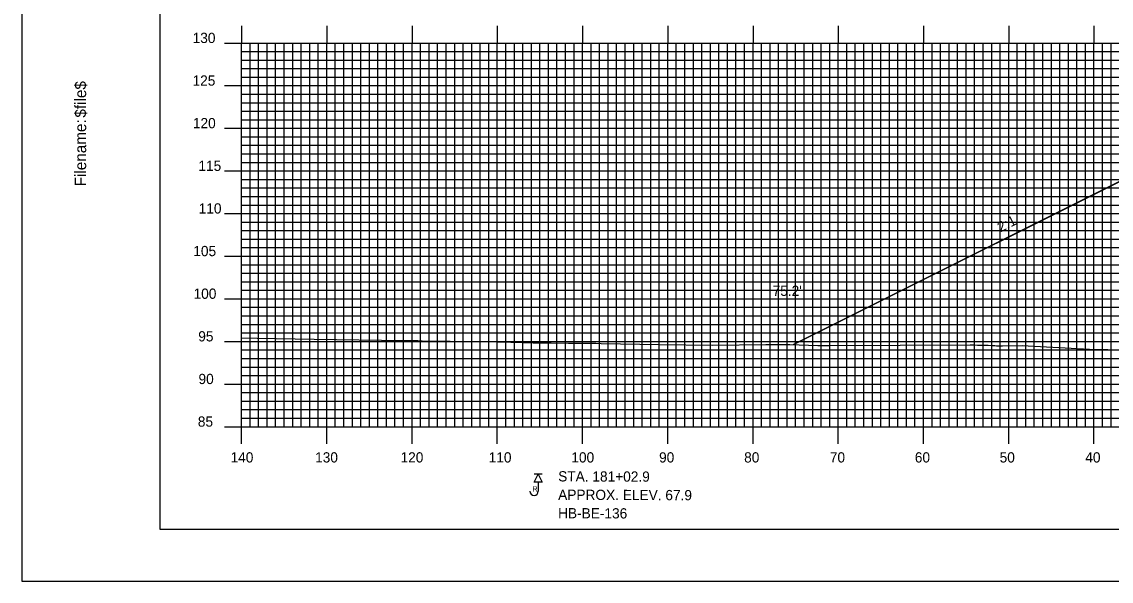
# Model space of a CAD drawing. Extents: x 1786189 to 1786532, y 442591 to 442811.
# Drawn here: x 1786188.8 to 1786316.6, y 442590.5 to 442656.2 of the extents above; entities that cross this region are included whole.
import ezdxf

# ---------------------------------------------------------------- set-up
doc = ezdxf.new("R2010")
doc.units = 0
for name, color, linetype in [('ANNOTATION', 7, 'Continuous'), ('BORDER', 7, 'Continuous'), ('BORING - REFUSAL', 7, 'Continuous'), ('D_Roadway_Centerline', 7, 'Continuous'), ('D_Roadway_SlopeLines', 7, 'Continuous'), ('D_Text_Standard', 7, 'Continuous'), ('H_V ANNOTATION', 7, 'Continuous'), ('MAJOR', 7, 'Continuous'), ('MINOR', 7, 'Continuous'), ('PLOT BOUNDARY', 7, 'Continuous'), ('S_Roadway_Centerline', 7, 'Continuous')]:
    doc.layers.add(name, color=color, linetype=linetype)

msp = doc.modelspace()

# ---------------------------------------------------------------- linework, layer by layer
at = {"layer": 'BORDER'}
msp.add_lwpolyline([(1786204.96, 442596.67), (1786524.96, 442596.67), (1786524.96, 442806.67), (1786204.96, 442806.67)], close=True, dxfattribs=at)
at = {"layer": 'BORING - REFUSAL'}
for p, q in [((1786249.84, 442603.12), (1786248.89, 442603.12)), ((1786249.36, 442602.16), (1786249.36, 442601.1))]:
    msp.add_line(p, q, dxfattribs=at)
msp.add_lwpolyline([(1786249.36, 442603.12), (1786249.84, 442602.16), (1786248.89, 442602.16)], close=True, dxfattribs=at)
msp.add_arc((1786248.88, 442601.1), 0.485, 180, 0, dxfattribs=at)
at = {"layer": 'D_Roadway_Centerline'}
msp.add_lwpolyline([(1786279.32, 442618.29), (1786326.75, 442642), (1786331.56, 442644.41), (1786334.56, 442644.53), (1786342.56, 442644.85), (1786354.56, 442645.11), (1786366.56, 442645.37), (1786374.56, 442645.05), (1786377.56, 442644.93), (1786382.31, 442642.56), (1786433.18, 442617.13)], dxfattribs=at)
at = {"layer": 'D_Roadway_SlopeLines'}
msp.add_lwpolyline([(1786331.56, 442644.41), (1786279.32, 442618.29)], dxfattribs=at)
at = {"layer": 'MAJOR'}
for p, q in [((1786214.56, 442655.67), (1786214.56, 442653.67)), ((1786224.56, 442655.67), (1786224.56, 442653.67)), ((1786234.56, 442655.67), (1786234.56, 442653.67)), ((1786244.56, 442655.67), (1786244.56, 442653.67)), ((1786254.56, 442655.67), (1786254.56, 442653.67)), ((1786264.56, 442655.67), (1786264.56, 442653.67)), ((1786274.56, 442655.67), (1786274.56, 442653.67)), ((1786284.56, 442655.67), (1786284.56, 442653.67)), ((1786294.56, 442655.67), (1786294.56, 442653.67)), ((1786304.56, 442655.67), (1786304.56, 442653.67)), ((1786314.56, 442655.67), (1786314.56, 442653.67)), ((1786212.56, 442653.67), (1786214.56, 442653.67)), ((1786214.56, 442653.67), (1786494.56, 442653.67)), ((1786214.56, 442608.67), (1786214.56, 442653.67)), ((1786214.56, 442608.67), (1786214.56, 442653.67)), ((1786214.56, 442653.67), (1786494.56, 442653.67)), ((1786224.56, 442608.67), (1786224.56, 442653.67)), ((1786234.56, 442608.67), (1786234.56, 442653.67)), ((1786244.56, 442608.67), (1786244.56, 442653.67)), ((1786254.56, 442608.67), (1786254.56, 442653.67)), ((1786264.56, 442608.67), (1786264.56, 442653.67)), ((1786274.56, 442608.67), (1786274.56, 442653.67)), ((1786284.56, 442608.67), (1786284.56, 442653.67)), ((1786294.56, 442608.67), (1786294.56, 442653.67)), ((1786304.56, 442608.67), (1786304.56, 442653.67)), ((1786314.56, 442608.67), (1786314.56, 442653.67)), ((1786212.56, 442648.67), (1786214.56, 442648.67)), ((1786214.56, 442648.67), (1786494.56, 442648.67)), ((1786212.56, 442643.67), (1786214.56, 442643.67)), ((1786214.56, 442643.67), (1786494.56, 442643.67)), ((1786212.56, 442638.67), (1786214.56, 442638.67)), ((1786214.56, 442638.67), (1786494.56, 442638.67)), ((1786212.56, 442633.67), (1786214.56, 442633.67)), ((1786214.56, 442633.67), (1786494.56, 442633.67)), ((1786212.56, 442628.67), (1786214.56, 442628.67)), ((1786214.56, 442628.67), (1786494.56, 442628.67)), ((1786212.56, 442623.67), (1786214.56, 442623.67)), ((1786214.56, 442623.67), (1786494.56, 442623.67)), ((1786212.56, 442618.67), (1786214.56, 442618.67)), ((1786214.56, 442618.67), (1786494.56, 442618.67)), ((1786212.56, 442613.67), (1786214.56, 442613.67)), ((1786214.56, 442613.67), (1786494.56, 442613.67)), ((1786212.56, 442608.67), (1786214.56, 442608.67)), ((1786214.56, 442608.67), (1786494.56, 442608.67)), ((1786214.56, 442608.67), (1786494.56, 442608.67)), ((1786214.56, 442606.66), (1786214.56, 442608.67)), ((1786224.56, 442606.66), (1786224.56, 442608.67)), ((1786234.56, 442606.66), (1786234.56, 442608.67)), ((1786244.56, 442606.66), (1786244.56, 442608.67)), ((1786254.56, 442606.66), (1786254.56, 442608.67)), ((1786264.56, 442606.66), (1786264.56, 442608.67)), ((1786274.56, 442606.66), (1786274.56, 442608.67)), ((1786284.56, 442606.66), (1786284.56, 442608.67)), ((1786294.56, 442606.66), (1786294.56, 442608.67)), ((1786304.56, 442606.66), (1786304.56, 442608.67)), ((1786314.56, 442606.66), (1786314.56, 442608.67))]:
    msp.add_line(p, q, dxfattribs=at)
at = {"layer": 'MINOR'}
for p, q in [((1786214.56, 442652.67), (1786494.56, 442652.67)), ((1786214.56, 442652.67), (1786216.57, 442652.67)), ((1786215.56, 442608.67), (1786215.56, 442653.67)), ((1786216.56, 442608.67), (1786216.56, 442653.67)), ((1786217.56, 442608.67), (1786217.56, 442653.67)), ((1786218.56, 442608.67), (1786218.56, 442653.67)), ((1786219.56, 442608.67), (1786219.56, 442653.67)), ((1786220.56, 442608.67), (1786220.56, 442653.67)), ((1786221.56, 442608.67), (1786221.56, 442653.67)), ((1786222.56, 442608.67), (1786222.56, 442653.67)), ((1786223.56, 442608.67), (1786223.56, 442653.67)), ((1786225.56, 442608.67), (1786225.56, 442653.67)), ((1786226.56, 442608.67), (1786226.56, 442653.67)), ((1786227.56, 442608.67), (1786227.56, 442653.67)), ((1786228.56, 442608.67), (1786228.56, 442653.67)), ((1786229.56, 442608.67), (1786229.56, 442653.67)), ((1786230.56, 442608.67), (1786230.56, 442653.67)), ((1786231.56, 442608.67), (1786231.56, 442653.67)), ((1786232.56, 442608.67), (1786232.56, 442653.67)), ((1786233.56, 442608.67), (1786233.56, 442653.67)), ((1786235.56, 442608.67), (1786235.56, 442653.67)), ((1786236.56, 442608.67), (1786236.56, 442653.67)), ((1786237.56, 442608.67), (1786237.56, 442653.67)), ((1786238.56, 442608.67), (1786238.56, 442653.67)), ((1786239.56, 442608.67), (1786239.56, 442653.67)), ((1786240.56, 442608.67), (1786240.56, 442653.67)), ((1786241.56, 442608.67), (1786241.56, 442653.67)), ((1786242.56, 442608.67), (1786242.56, 442653.67)), ((1786243.56, 442608.67), (1786243.56, 442653.67)), ((1786245.56, 442608.67), (1786245.56, 442653.67)), ((1786246.56, 442608.67), (1786246.56, 442653.67)), ((1786247.56, 442608.67), (1786247.56, 442653.67)), ((1786248.56, 442608.67), (1786248.56, 442653.67)), ((1786249.56, 442608.67), (1786249.56, 442653.67)), ((1786250.56, 442608.67), (1786250.56, 442653.67)), ((1786251.56, 442608.67), (1786251.56, 442653.67)), ((1786252.56, 442608.67), (1786252.56, 442653.67)), ((1786253.56, 442608.67), (1786253.56, 442653.67)), ((1786255.56, 442608.67), (1786255.56, 442653.67)), ((1786256.56, 442608.67), (1786256.56, 442653.67)), ((1786257.56, 442608.67), (1786257.56, 442653.67)), ((1786258.56, 442608.67), (1786258.56, 442653.67)), ((1786259.56, 442608.67), (1786259.56, 442653.67)), ((1786260.56, 442608.67), (1786260.56, 442653.67)), ((1786261.56, 442608.67), (1786261.56, 442653.67)), ((1786262.56, 442608.67), (1786262.56, 442653.67)), ((1786263.56, 442608.67), (1786263.56, 442653.67)), ((1786265.56, 442608.67), (1786265.56, 442653.67)), ((1786266.56, 442608.67), (1786266.56, 442653.67)), ((1786267.56, 442608.67), (1786267.56, 442653.67)), ((1786268.56, 442608.67), (1786268.56, 442653.67)), ((1786269.56, 442608.67), (1786269.56, 442653.67)), ((1786270.56, 442608.67), (1786270.56, 442653.67)), ((1786271.56, 442608.67), (1786271.56, 442653.67)), ((1786272.56, 442608.67), (1786272.56, 442653.67)), ((1786273.56, 442608.67), (1786273.56, 442653.67)), ((1786275.56, 442608.67), (1786275.56, 442653.67)), ((1786276.56, 442608.67), (1786276.56, 442653.67)), ((1786277.56, 442608.67), (1786277.56, 442653.67)), ((1786278.56, 442608.67), (1786278.56, 442653.67)), ((1786279.56, 442608.67), (1786279.56, 442653.67)), ((1786280.56, 442608.67), (1786280.56, 442653.67)), ((1786281.56, 442608.67), (1786281.56, 442653.67)), ((1786282.56, 442608.67), (1786282.56, 442653.67)), ((1786283.56, 442608.67), (1786283.56, 442653.67)), ((1786285.56, 442608.67), (1786285.56, 442653.67)), ((1786286.56, 442608.67), (1786286.56, 442653.67)), ((1786287.56, 442608.67), (1786287.56, 442653.67)), ((1786288.56, 442608.67), (1786288.56, 442653.67)), ((1786289.56, 442608.67), (1786289.56, 442653.67)), ((1786290.56, 442608.67), (1786290.56, 442653.67)), ((1786291.56, 442608.67), (1786291.56, 442653.67)), ((1786292.56, 442608.67), (1786292.56, 442653.67)), ((1786293.56, 442608.67), (1786293.56, 442653.67)), ((1786295.56, 442608.67), (1786295.56, 442653.67)), ((1786296.56, 442608.67), (1786296.56, 442653.67)), ((1786297.56, 442608.67), (1786297.56, 442653.67)), ((1786298.56, 442608.67), (1786298.56, 442653.67)), ((1786299.56, 442608.67), (1786299.56, 442653.67)), ((1786300.56, 442608.67), (1786300.56, 442653.67)), ((1786301.56, 442608.67), (1786301.56, 442653.67)), ((1786302.56, 442608.67), (1786302.56, 442653.67)), ((1786303.56, 442608.67), (1786303.56, 442653.67)), ((1786305.56, 442608.67), (1786305.56, 442653.67)), ((1786306.56, 442608.67), (1786306.56, 442653.67)), ((1786307.56, 442608.67), (1786307.56, 442653.67)), ((1786308.56, 442608.67), (1786308.56, 442653.67)), ((1786309.56, 442608.67), (1786309.56, 442653.67)), ((1786310.56, 442608.67), (1786310.56, 442653.67)), ((1786311.56, 442608.67), (1786311.56, 442653.67)), ((1786312.56, 442608.67), (1786312.56, 442653.67)), ((1786313.56, 442608.67), (1786313.56, 442653.67)), ((1786315.56, 442608.67), (1786315.56, 442653.67)), ((1786316.56, 442608.67), (1786316.56, 442653.67)), ((1786214.56, 442651.67), (1786494.56, 442651.67)), ((1786214.56, 442651.67), (1786216.57, 442651.67)), ((1786214.56, 442650.67), (1786494.56, 442650.67)), ((1786214.56, 442650.67), (1786216.57, 442650.67)), ((1786214.56, 442649.67), (1786494.56, 442649.67)), ((1786214.56, 442649.67), (1786216.57, 442649.67)), ((1786214.56, 442647.67), (1786494.56, 442647.67)), ((1786214.56, 442647.67), (1786216.57, 442647.67)), ((1786214.56, 442646.67), (1786494.56, 442646.67)), ((1786214.56, 442646.67), (1786216.57, 442646.67)), ((1786214.56, 442645.67), (1786494.56, 442645.67)), ((1786214.56, 442645.67), (1786216.57, 442645.67)), ((1786214.56, 442644.67), (1786494.56, 442644.67)), ((1786214.56, 442644.67), (1786216.57, 442644.67)), ((1786214.56, 442642.67), (1786494.56, 442642.67)), ((1786214.56, 442642.67), (1786216.57, 442642.67)), ((1786214.56, 442641.67), (1786494.56, 442641.67)), ((1786214.56, 442641.67), (1786216.57, 442641.67)), ((1786214.56, 442640.67), (1786494.56, 442640.67)), ((1786214.56, 442640.67), (1786216.57, 442640.67)), ((1786214.56, 442639.67), (1786494.56, 442639.67)), ((1786214.56, 442639.67), (1786216.57, 442639.67)), ((1786214.56, 442637.67), (1786494.56, 442637.67)), ((1786214.56, 442637.67), (1786216.57, 442637.67)), ((1786214.56, 442636.67), (1786494.56, 442636.67)), ((1786214.56, 442636.67), (1786216.57, 442636.67)), ((1786214.56, 442635.67), (1786494.56, 442635.67)), ((1786214.56, 442635.67), (1786216.57, 442635.67)), ((1786214.56, 442634.67), (1786494.56, 442634.67)), ((1786214.56, 442634.67), (1786216.57, 442634.67)), ((1786214.56, 442632.67), (1786494.56, 442632.67)), ((1786214.56, 442632.67), (1786216.57, 442632.67)), ((1786214.56, 442631.67), (1786494.56, 442631.67)), ((1786214.56, 442631.67), (1786216.57, 442631.67)), ((1786214.56, 442630.67), (1786494.56, 442630.67)), ((1786214.56, 442630.67), (1786216.57, 442630.67)), ((1786214.56, 442629.67), (1786494.56, 442629.67)), ((1786214.56, 442629.67), (1786216.57, 442629.67)), ((1786214.56, 442627.67), (1786494.56, 442627.67)), ((1786214.56, 442627.67), (1786216.57, 442627.67)), ((1786214.56, 442626.67), (1786494.56, 442626.67)), ((1786214.56, 442626.67), (1786216.57, 442626.67)), ((1786214.56, 442625.67), (1786494.56, 442625.67)), ((1786214.56, 442625.67), (1786216.57, 442625.67)), ((1786214.56, 442624.67), (1786494.56, 442624.67)), ((1786214.56, 442624.67), (1786216.57, 442624.67)), ((1786214.56, 442622.67), (1786494.56, 442622.67)), ((1786214.56, 442622.67), (1786216.57, 442622.67)), ((1786214.56, 442621.67), (1786494.56, 442621.67)), ((1786214.56, 442621.67), (1786216.57, 442621.67)), ((1786214.56, 442620.67), (1786494.56, 442620.67)), ((1786214.56, 442620.67), (1786216.57, 442620.67)), ((1786214.56, 442619.67), (1786494.56, 442619.67)), ((1786214.56, 442619.67), (1786216.57, 442619.67)), ((1786214.56, 442617.67), (1786494.56, 442617.67)), ((1786214.56, 442617.67), (1786216.57, 442617.67)), ((1786214.56, 442616.67), (1786494.56, 442616.67)), ((1786214.56, 442616.67), (1786216.57, 442616.67)), ((1786214.56, 442615.67), (1786494.56, 442615.67)), ((1786214.56, 442615.67), (1786216.57, 442615.67)), ((1786214.56, 442614.67), (1786494.56, 442614.67)), ((1786214.56, 442614.67), (1786216.57, 442614.67)), ((1786214.56, 442612.67), (1786494.56, 442612.67)), ((1786214.56, 442612.67), (1786216.57, 442612.67)), ((1786214.56, 442611.67), (1786494.56, 442611.67)), ((1786214.56, 442611.67), (1786216.57, 442611.67)), ((1786214.56, 442610.67), (1786494.56, 442610.67)), ((1786214.56, 442610.67), (1786216.57, 442610.67)), ((1786214.56, 442609.67), (1786494.56, 442609.67)), ((1786214.56, 442609.67), (1786216.57, 442609.67))]:
    msp.add_line(p, q, dxfattribs=at)
at = {"layer": 'PLOT BOUNDARY'}
msp.add_lwpolyline([(1786188.78, 442590.55), (1786528.78, 442590.55), (1786528.78, 442810.55), (1786188.78, 442810.55)], close=True, dxfattribs=at)
at = {"layer": 'S_Roadway_Centerline'}
msp.add_lwpolyline([(1786214.56, 442619.08), (1786216.39, 442619.05), (1786223.08, 442618.95), (1786233.58, 442618.78), (1786233.92, 442618.77), (1786234.31, 442618.77), (1786234.74, 442618.76), (1786235.22, 442618.76), (1786235.74, 442618.75), (1786242.33, 442618.68), (1786243.04, 442618.68), (1786246.13, 442618.6), (1786248.76, 442618.52), (1786250.88, 442618.5), (1786252.92, 442618.48), (1786253.84, 442618.47), (1786254.68, 442618.46), (1786255.44, 442618.45), (1786256.13, 442618.45), (1786256.74, 442618.44), (1786263.54, 442618.3), (1786269.84, 442618.23), (1786276.05, 442618.29), (1786278.86, 442618.3), (1786282.15, 442618.19), (1786282.33, 442618.19), (1786282.51, 442618.19), (1786282.69, 442618.19), (1786282.87, 442618.19), (1786283.04, 442618.19), (1786283.19, 442618.18), (1786283.4, 442618.18), (1786283.62, 442618.18), (1786300.03, 442618.26), (1786300.19, 442618.26), (1786300.36, 442618.26), (1786300.53, 442618.26), (1786300.88, 442618.25), (1786301.05, 442618.25), (1786301.79, 442618.23), (1786301.96, 442618.23), (1786302.14, 442618.22), (1786302.51, 442618.2), (1786302.71, 442618.19), (1786302.91, 442618.18), (1786303.11, 442618.17), (1786303.3, 442618.17), (1786303.47, 442618.16), (1786303.65, 442618.16), (1786303.84, 442618.16), (1786306.14, 442618.21), (1786314.04, 442617.77), (1786324.86, 442617.57)], dxfattribs=at)

# ---------------------------------------------------------------- texts
at = {"layer": 'ANNOTATION'}
msp.add_text('2:1', height=1.2, rotation=26.5651, dxfattribs=at).set_placement((1786303.59, 442631.45))
at = {"layer": 'BORDER'}
for s, p in [('$file$', (1786196.33, 442644.92)), ('Filename:', (1786196.33, 442636.86))]:
    msp.add_text(s, height=1.339, rotation=90, dxfattribs=at).set_placement(p)
at = {"layer": 'BORING - REFUSAL'}
for s, p in [('STA. 181+02.9', (1786251.7, 442602.25)), ('APPROX. ELEV. 67.9', (1786251.7, 442600.09)), ('HB-BE-136', (1786251.69, 442597.93))]:
    msp.add_text(s, height=1.2, rotation=359.8142, dxfattribs=at).set_placement(p)
msp.add_text('R', height=0.64, dxfattribs=at).set_placement((1786248.66, 442601.05))
at = {"layer": 'D_Text_Standard'}
msp.add_text("75.2'", height=1.2, dxfattribs=at).set_placement((1786276.86, 442624.01))
at = {"layer": 'H_V ANNOTATION'}
for s, p in [('130', (1786208.82, 442653.67)), ('125', (1786208.81, 442648.67)), ('120', (1786208.85, 442643.67)), ('115', (1786209.5, 442638.67)), ('110', (1786209.53, 442633.67)), ('105', (1786208.9, 442628.67)), ('100', (1786208.93, 442623.67)), ('95', (1786209.48, 442618.67)), ('90', (1786209.51, 442613.67)), ('85', (1786209.43, 442608.67)), ('140', (1786213.27, 442604.47)), ('130', (1786223.19, 442604.47)), ('120', (1786233.21, 442604.47)), ('110', (1786243.55, 442604.47)), ('100', (1786253.25, 442604.47)), ('90', (1786263.54, 442604.47)), ('80', (1786273.52, 442604.47)), ('70', (1786283.57, 442604.47)), ('60', (1786293.54, 442604.47)), ('50', (1786303.49, 442604.47)), ('40', (1786313.54, 442604.47))]:
    msp.add_text(s, height=1.2, dxfattribs=at).set_placement(p)
at = {"layer": 'MAJOR'}
msp.add_text('-', height=0.012, dxfattribs=at).set_placement((1786214.56, 442608.67))

doc.saveas('drawing.dxf')
